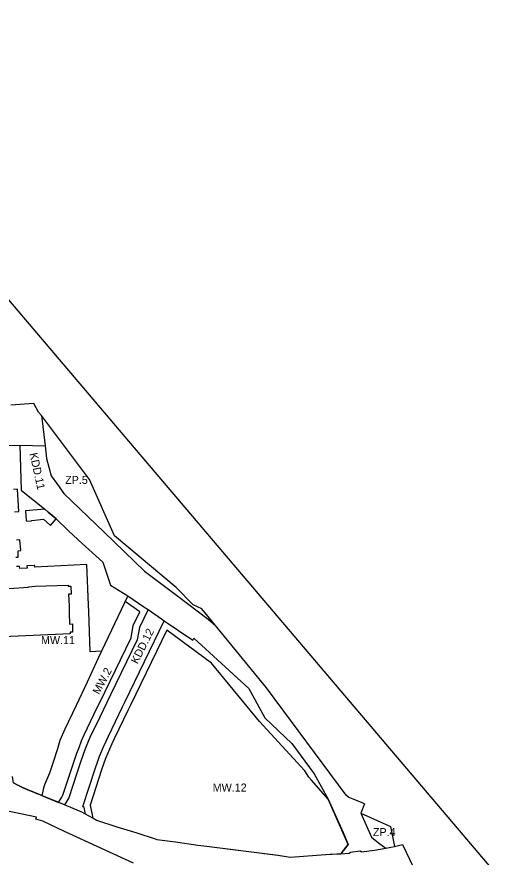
# Model space of a CAD drawing. Extents: x 7424719 to 7426158, y 5545504 to 5546892.
# Drawn here: x 7425369 to 7425675, y 5545910 to 5546434 of the extents above; entities that cross this region are included whole.
import ezdxf

# ---------------------------------------------------------------- set-up
doc = ezdxf.new("R2010")
doc.units = 0
for name, color, linetype in [('Linia Zabudowy Nieprzekraczalna', 7, 'Continuous'), ('Linia Zabudowy Obowiązujaca', 7, 'Continuous'), ('Linie Rozgraniczajace', 7, 'Continuous'), ('Oznaczenia Przeznaczenia', 7, 'Continuous')]:
    doc.layers.add(name, color=color, linetype=linetype)

msp = doc.modelspace()

# ---------------------------------------------------------------- linework, layer by layer
at = {"layer": 'Linia Zabudowy Nieprzekraczalna'}
for points in [[(7425445.43, 5546062.78), (7425436.17, 5546069.13)], [(7425394.64, 5545943.7), (7425396.61, 5545946.93), (7425397.39, 5545948.23), (7425402.35, 5545963.34), (7425404.77, 5545970.72), (7425406.04, 5545974.41), (7425407.41, 5545978.08), (7425409.07, 5545982.27), (7425410.63, 5545985.88), (7425416.76, 5545998.71), (7425423.49, 5546012.61), (7425439.95, 5546046.57), (7425441.29, 5546054.24), (7425445.43, 5546062.78)], [(7425550.88, 5545959.44), (7425550.81, 5545959.53), (7425548.43, 5545963.56), (7425520.09, 5545994.18), (7425490.16, 5546030.73), (7425462.25, 5546051.29), (7425439.58, 5546004.52), (7425438.18, 5546001.64), (7425429.34, 5545983.43), (7425427.91, 5545980.4), (7425426.36, 5545976.91), (7425425.32, 5545974.41), (7425424.02, 5545971.12), (7425422.75, 5545967.59), (7425421.51, 5545964.03), (7425414.33, 5545942.03), (7425416.06, 5545933.93)], [(7425421.51, 5546038.18), (7425414.45, 5546037.81)], [(7425565.52, 5545911.39), (7425571.08, 5545911.72), (7425575.5, 5545917.51), (7425563.04, 5545945.85), (7425552.49, 5545957.65), (7425550.88, 5545959.45)], [(7425531.64, 5545910.7), (7425539.31, 5545909.58), (7425564.2, 5545911.32), (7425565.52, 5545911.39), (7425565.52, 5545911.39)]]:
    msp.add_lwpolyline(points, dxfattribs=at)
at = {"layer": 'Linia Zabudowy Obowiązujaca'}
for points in [[(7425367.07, 5546125.3), (7425369.91, 5546125.54), (7425369.07, 5546139.39), (7425366.62, 5546139.21)], [(7425368.01, 5546096.89), (7425369.45, 5546096.96), (7425369.33, 5546100.94), (7425371.19, 5546101.01), (7425370.53, 5546107.66), (7425368.33, 5546107.56)], [(7425414.45, 5546037.81), (7425413.48, 5546063.05), (7425413.27, 5546067.04), (7425412.36, 5546092.25), (7425379.78, 5546090.71), (7425379.78, 5546091.63), (7425379.43, 5546091.64), (7425374.9, 5546091.53), (7425374.96, 5546090.05), (7425370.42, 5546089.75), (7425370.35, 5546091.08), (7425368.3, 5546091)], [(7425363.55, 5546077.33), (7425375.97, 5546078.17), (7425375.95, 5546078.46), (7425380.07, 5546078.73), (7425400.74, 5546079.52), (7425400.73, 5546078.72), (7425402.41, 5546078.8), (7425402.58, 5546073.83), (7425400.9, 5546073.8), (7425401.17, 5546066.38), (7425401.22, 5546062.39), (7425401.56, 5546055.08), (7425403.3, 5546055.2), (7425403.44, 5546050.09), (7425401.81, 5546049.99), (7425401.86, 5546049.12), (7425360.31, 5546047.06)], [(7425366.55, 5545956.02), (7425368.74, 5545954.71), (7425372.07, 5545953.06), (7425374.97, 5545951.87), (7425384.21, 5545948.03), (7425384.72, 5545947.84), (7425394.64, 5545943.7)], [(7425441.52, 5545905.84), (7425406, 5545922.06), (7425398.41, 5545925.48), (7425384.75, 5545932.02), (7425380.53, 5545933.18), (7425380.79, 5545934.47), (7425361.98, 5545938.37), (7425355.08, 5545935.83), (7425344.31, 5545931.84), (7425340.9, 5545926.19)], [(7425416.06, 5545933.93), (7425418.36, 5545932.69), (7425431.04, 5545928.46), (7425443.43, 5545924.81), (7425454.9, 5545920.91), (7425455.95, 5545920.54), (7425467.55, 5545919.03), (7425481.49, 5545917.08), (7425485.42, 5545916.66), (7425531.64, 5545910.7)]]:
    msp.add_lwpolyline(points, dxfattribs=at)
msp.add_lwpolyline([(7425386.02, 5546126.86), (7425374.01, 5546125.81), (7425374.38, 5546119.84), (7425374.85, 5546119.43), (7425377.46, 5546119.55), (7425377.88, 5546119.91), (7425385.24, 5546120.56), (7425389.61, 5546116.72), (7425393.14, 5546120.91), (7425391.73, 5546122.09), (7425388.17, 5546125.06)], close=True, dxfattribs=at)
at = {"layer": 'Linie Rozgraniczajace'}
for p, q in [((7425978.47, 5545533.55), (7425205.67, 5546443.4)), ((7425370.49, 5546166.85), (7425386.19, 5546166.46)), ((7425374.97, 5545951.87), (7425372.07, 5545953.06)), ((7425585.72, 5545942.88), (7425583.27, 5545937.04)), ((7425583.27, 5545937.04), (7425599.47, 5545929.76)), ((7425599.47, 5545929.76), (7425601.76, 5545928.72)), ((7425601.76, 5545928.72), (7425604.31, 5545916.26))]:
    msp.add_line(p, q, dxfattribs=at)
for points in [[(7425413.86, 5546145.47), (7425383.99, 5546185.44), (7425382.18, 5546187.57), (7425379.14, 5546192.91), (7425364.88, 5546191.88)], [(7425383.99, 5546185.44), (7425386.19, 5546166.46), (7425387.1, 5546158.6), (7425388.55, 5546153.17), (7425390, 5546147.74), (7425393.98, 5546142.24), (7425397.96, 5546136.73), (7425423.11, 5546112.45), (7425448.26, 5546088.17), (7425468.2, 5546073.16), (7425488.14, 5546058.16), (7425492.55, 5546054.25)], [(7425352.24, 5546166.59), (7425370.49, 5546166.85), (7425371.33, 5546138.77), (7425386.02, 5546126.86), (7425388.17, 5546125.06), (7425391.73, 5546122.09), (7425393.14, 5546120.91), (7425400.85, 5546113.46), (7425406.72, 5546108.04), (7425407.18, 5546107.63), (7425422.32, 5546093.78), (7425427.13, 5546079.45), (7425437.9, 5546072.79), (7425447.88, 5546065.95), (7425450.54, 5546064.14), (7425458.82, 5546058.46), (7425460.67, 5546057.2), (7425478.47, 5546045.13), (7425479.01, 5546046.26), (7425513.47, 5546014.95), (7425523.31, 5545996.64), (7425540.18, 5545980.58)], [(7425478.58, 5546067.11), (7425467.99, 5546077.91), (7425429.51, 5546110.26), (7425413.86, 5546145.47)], [(7425437.9, 5546072.79), (7425419.45, 5546033.83), (7425412.58, 5546018.85), (7425405.73, 5546004.26), (7425398.59, 5545989.56), (7425395.41, 5545982.36), (7425394.06, 5545977.14), (7425391.37, 5545968.81), (7425389.03, 5545962.1), (7425385.8, 5545954.71), (7425385.33, 5545952.74), (7425384.86, 5545950.76), (7425384.21, 5545948.03)], [(7425450.54, 5546064.14), (7425445.13, 5546053), (7425443.79, 5546045.33), (7425427.09, 5546010.87), (7425420.36, 5545996.98), (7425414.27, 5545984.23), (7425412.77, 5545980.74), (7425411.14, 5545976.64), (7425409.81, 5545973.06), (7425408.56, 5545969.44), (7425406.15, 5545962.09), (7425401.05, 5545946.56), (7425400.03, 5545944.86), (7425398.37, 5545942.14)], [(7425524.38, 5546015.36), (7425492.55, 5546054.25), (7425484.05, 5546064.64), (7425478.58, 5546067.11)], [(7425418.36, 5545932.69), (7425411.44, 5545936.41), (7425410.55, 5545940.57), (7425409.85, 5545941.2), (7425417.72, 5545965.31), (7425418.98, 5545968.93), (7425420.28, 5545972.53), (7425421.61, 5545975.92), (7425422.69, 5545978.49), (7425424.27, 5545982.06), (7425425.73, 5545985.16), (7425434.58, 5546003.39), (7425435.98, 5546006.27), (7425460.67, 5546057.2)], [(7425585.72, 5545942.88), (7425580.13, 5545945.12), (7425575.76, 5545946.88), (7425574.16, 5545948.2), (7425524.38, 5546015.36)], [(7425540.18, 5545980.58), (7425554.28, 5545961.52), (7425563.04, 5545945.85), (7425572.25, 5545924.9), (7425575.5, 5545917.51), (7425570.85, 5545911.67)], [(7425372.07, 5545953.06), (7425368.74, 5545954.71), (7425366.55, 5545956.02), (7425366.09, 5545958.45), (7425365.83, 5545959.82)], [(7425384.21, 5545948.03), (7425374.97, 5545951.87)], [(7425411.44, 5545936.41), (7425408.75, 5545937.8), (7425407.63, 5545938.27), (7425398.37, 5545942.14), (7425384.72, 5545947.84), (7425384.21, 5545948.03)], [(7425441.52, 5545905.84), (7425406, 5545922.06), (7425398.41, 5545925.48), (7425384.75, 5545932.02), (7425380.53, 5545933.18), (7425380.79, 5545934.47), (7425361.98, 5545938.37), (7425355.08, 5545935.83), (7425344.31, 5545931.84), (7425340.9, 5545926.19)], [(7425583.27, 5545937.04), (7425586.59, 5545929.58), (7425589.92, 5545921.97), (7425594.46, 5545918.57), (7425599, 5545915.17)], [(7425418.36, 5545932.69), (7425431.04, 5545928.46), (7425443.43, 5545924.81), (7425454.9, 5545920.91), (7425455.95, 5545920.54), (7425467.55, 5545919.03), (7425481.49, 5545917.08), (7425485.42, 5545916.66), (7425531.52, 5545910.72), (7425539.31, 5545909.58), (7425564.2, 5545911.32), (7425570.85, 5545911.67), (7425576.11, 5545911.95), (7425576.81, 5545912.72), (7425582.96, 5545913.42), (7425583.81, 5545912.81), (7425591.77, 5545913.83), (7425599, 5545915.17), (7425601.99, 5545915.73), (7425604.31, 5545916.26), (7425609.38, 5545917.44), (7425616.05, 5545903.52)]]:
    msp.add_lwpolyline(points, dxfattribs=at)

# ---------------------------------------------------------------- texts
at = {"layer": 'Oznaczenia Przeznaczenia'}
for s, rotation, p in [('KDD.11', 282.3621, (7425376.5, 5546161.58)), ('KDD.12', 63.2976, (7425443.94, 5546029.83)), ('MW.2', 62.1846, (7425419.97, 5546010.73))]:
    msp.add_text(s, height=5, rotation=rotation, dxfattribs=at).set_placement(p)
for s, p in [('ZP.5', (7425398.77, 5546142.66)), ('MW.11', (7425383.7, 5546042.59)), ('MW.12', (7425490.88, 5545950.52)), ('ZP.4', (7425590.87, 5545922.69))]:
    msp.add_text(s, height=5, dxfattribs=at).set_placement(p)

doc.saveas('drawing.dxf')
